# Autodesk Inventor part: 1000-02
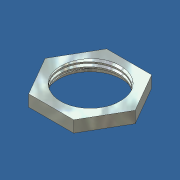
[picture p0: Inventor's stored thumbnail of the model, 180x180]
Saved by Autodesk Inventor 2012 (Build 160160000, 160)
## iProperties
Created: 2007-03
Part Number: 1000-02
Document SubType Name: Modeling
Designer: Andy Moles
Material: Steel
Mass: 8.73625 g
Surface Area: 13.3576 cm^2
Volume: 1.1129 cm^3
Density: 7.85 g/cm^3
Author: Andy Moles
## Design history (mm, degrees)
feature "Base1"
body "Solid1"
